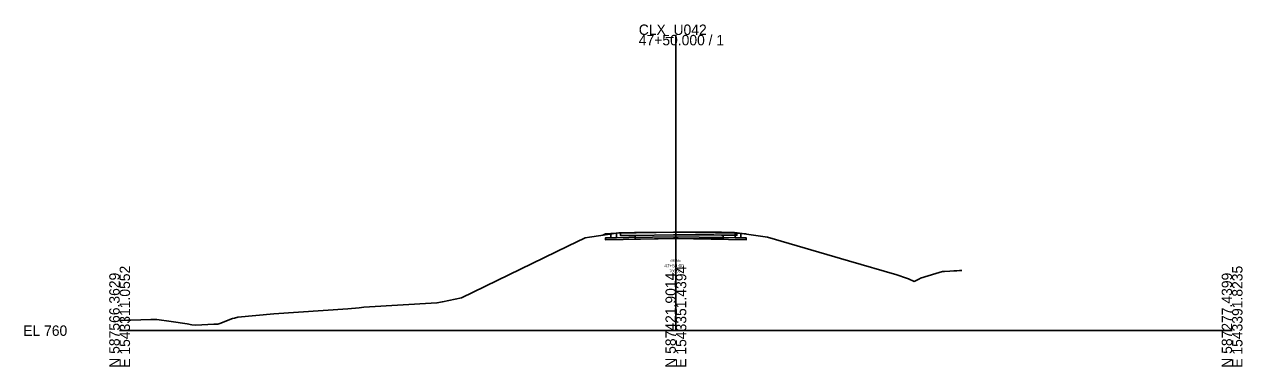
# Model space of a CAD drawing. Extents: x -26 to 1603, y -10 to 5557.
# Drawn here: x -25.7 to 302.8, y 3490.3 to 3582.5 of the extents above; entities that cross this region are included whole.
import ezdxf

# ---------------------------------------------------------------- set-up
doc = ezdxf.new("R2010")
doc.units = 0
for name, color, linetype in [('GK_Cells', 7, 'Continuous'), ('XS_P_Annotation', 7, 'Continuous'), ('XS_P_Earthwork_Shapes', 7, 'Continuous'), ('XS_P_Finished_Grade', 7, 'Continuous'), ('XS_P_Pavt_Layers', 7, 'Continuous'), ('XS_P_Pavt_Surface', 7, 'Continuous'), ('XS_P_Subgrade', 7, 'Continuous'), ('XS_X_Ground_Line', 7, 'Continuous'), ('XS_X_Pavt', 7, 'Continuous')]:
    doc.layers.add(name, color=color, linetype=linetype)

msp = doc.modelspace()

# ---------------------------------------------------------------- linework, layer by layer
at = {"layer": 'GK_Cells'}
for p, q in [((150, 3500), (150, 3579.69)), ((0, 3500), (150, 3500)), ((150, 3500), (300, 3500))]:
    msp.add_line(p, q, dxfattribs=at)
at = {"layer": 'XS_P_Earthwork_Shapes'}
for points in [[(131, 3526.05), (130.33, 3525.71), (134, 3526.28), (134, 3526.3)], [(134, 3526.3), (134, 3526.28), (130.33, 3525.71), (131, 3526.05)], [(131, 3526.05), (130.33, 3525.71), (132.5, 3526.05), (132.5, 3526.17)], [(131, 3525), (131, 3524.5), (150, 3524.8), (149.33, 3524.8), (139.01, 3524.66), (139.01, 3525.66), (138.82, 3525.66), (135.3, 3525.63), (135.11, 3525.63), (135.11, 3526.38), (134.65, 3526.37), (132.5, 3526.05), (132.5, 3525.02)], [(131, 3524.5), (150, 3524.8), (149.33, 3524.8), (139.01, 3524.66), (139.01, 3525.66), (138.82, 3525.66), (135.3, 3525.63), (135.11, 3525.63), (135.11, 3526.38), (134.65, 3526.37), (134, 3526.28), (134, 3525.05), (131, 3525)], [(131, 3524.5), (150, 3524.8), (149.33, 3524.8), (139.01, 3524.66), (139.01, 3525.66), (138.82, 3525.66), (135.3, 3525.63), (135.11, 3525.63), (135.11, 3526.38), (134.65, 3526.37), (134, 3526.28), (134, 3525.05), (131, 3525)], [(162.26, 3525.77), (162.76, 3525.76), (165.84, 3525.73), (166.44, 3525.65), (166.44, 3526.4), (165.84, 3526.48), (162.26, 3526.52), (160.23, 3526.53), (150.63, 3526.56), (150, 3526.55), (149.33, 3526.55), (138.82, 3526.41), (135.3, 3526.38), (135.11, 3526.38), (135.11, 3525.63), (135.3, 3525.63), (138.82, 3525.66), (139.01, 3525.66), (149.33, 3525.8), (150, 3525.8), (150.63, 3525.81), (160.23, 3525.78)], [(162.26, 3525.77), (162.76, 3525.76), (165.84, 3525.73), (166, 3525.71), (166, 3526.3), (166.44, 3526.26), (166.44, 3526.4), (165.84, 3526.48), (162.26, 3526.52), (160.23, 3526.53), (150.63, 3526.56), (150, 3526.55), (149.33, 3526.55), (138.82, 3526.41), (135.3, 3526.38), (135.11, 3526.38), (135.11, 3525.63), (135.3, 3525.63), (138.82, 3525.66), (139.01, 3525.66), (149.33, 3525.8), (150, 3525.8), (150.63, 3525.81), (160.23, 3525.78)], [(162.26, 3525.77), (162.76, 3525.76), (165.84, 3525.73), (166, 3525.71), (166, 3526.3), (166.44, 3526.26), (166.44, 3526.4), (165.84, 3526.48), (162.26, 3526.52), (160.23, 3526.53), (150.63, 3526.56), (150, 3526.55), (149.33, 3526.55), (138.82, 3526.41), (135.3, 3526.38), (135.11, 3526.38), (135.11, 3525.63), (135.3, 3525.63), (138.82, 3525.66), (139.01, 3525.66), (149.33, 3525.8), (150, 3525.8), (150.63, 3525.81), (160.23, 3525.78)], [(162.26, 3525.77), (162.76, 3525.76), (162.76, 3524.76), (162.26, 3524.77), (160.23, 3524.78), (150.63, 3524.81), (150, 3524.8), (149.33, 3524.8), (139.01, 3524.66), (139.01, 3525.66), (149.33, 3525.8), (150, 3525.8), (150.63, 3525.81), (160.23, 3525.78)], [(162.26, 3525.77), (162.76, 3525.76), (162.76, 3524.76), (162.26, 3524.77), (160.23, 3524.78), (150.63, 3524.81), (150, 3524.8), (149.33, 3524.8), (139.01, 3524.66), (139.01, 3525.66), (149.33, 3525.8), (150, 3525.8), (150.63, 3525.81), (160.23, 3525.78)], [(162.26, 3525.77), (162.76, 3525.76), (162.76, 3524.76), (162.26, 3524.77), (160.23, 3524.78), (150.63, 3524.81), (150, 3524.8), (149.33, 3524.8), (139.01, 3524.66), (139.01, 3525.66), (149.33, 3525.8), (150, 3525.8), (150.63, 3525.81), (160.23, 3525.78)], [(167.5, 3526.17), (168.69, 3526.07), (167.19, 3526.29), (166.44, 3526.4), (166.44, 3525.65), (165.84, 3525.73), (162.76, 3525.76), (162.76, 3524.76), (162.26, 3524.77), (160.23, 3524.78), (150.63, 3524.81), (150, 3524.8), (169, 3524.5), (169, 3525), (167.5, 3525.02)], [(150, 3524.8), (169, 3524.5), (169, 3525), (166, 3525.05), (166, 3525.71), (165.84, 3525.73), (162.76, 3525.76), (162.76, 3524.76), (162.26, 3524.77), (160.23, 3524.78), (150.63, 3524.81)], [(150, 3524.8), (169, 3524.5), (169, 3525), (166, 3525.05), (166, 3525.71), (165.84, 3525.73), (162.76, 3525.76), (162.76, 3524.76), (162.26, 3524.77), (160.23, 3524.78), (150.63, 3524.81)], [(166, 3526.3), (166.44, 3526.26), (166.44, 3525.65), (166, 3525.71)], [(166, 3526.3), (166.44, 3526.26), (166.44, 3525.65), (166, 3525.71)], [(167.19, 3526.29), (168.69, 3526.07), (166.44, 3526.26), (166.44, 3526.4)], [(167.19, 3526.29), (168.69, 3526.07), (166.44, 3526.26), (166.44, 3526.4)], [(169, 3526.05), (169.05, 3526.02), (168.69, 3526.07)], [(168.69, 3526.07), (169.05, 3526.02), (169, 3526.05)], [(168.69, 3526.07), (169.05, 3526.02), (169, 3526.05)]]:
    msp.add_lwpolyline(points, close=True, dxfattribs=at)
at = {"layer": 'XS_P_Finished_Grade'}
for p, q in [((131, 3526.05), (130.33, 3525.71)), ((134, 3526.3), (131, 3526.05)), ((166, 3526.3), (169, 3526.05)), ((169, 3526.05), (169.05, 3526.02))]:
    msp.add_line(p, q, dxfattribs=at)
at = {"layer": 'XS_P_Pavt_Layers'}
for p, q in [((150.02, 3525.3), (131, 3525)), ((134, 3526.3), (134, 3525.05)), ((149.98, 3525.3), (169, 3525)), ((166, 3526.3), (166, 3525.05)), ((131, 3524.5), (131, 3525)), ((150.03, 3524.8), (131, 3524.5)), ((149.97, 3524.8), (169, 3524.5)), ((169, 3524.5), (169, 3525))]:
    msp.add_line(p, q, dxfattribs=at)
at = {"layer": 'XS_P_Pavt_Surface'}
for q in [(134, 3526.3), (166, 3526.3)]:
    msp.add_line((150, 3526.55), q, dxfattribs=at)
at = {"layer": 'XS_P_Subgrade'}
msp.add_lwpolyline([(134, 3526.3), (134, 3525.05), (131, 3525), (131, 3524.5), (150, 3524.8), (169, 3524.5), (169, 3525), (166, 3525.05), (166, 3526.3)], dxfattribs=at)
at = {"layer": 'XS_X_Ground_Line'}
msp.add_lwpolyline([(0, 3502.74), (2.25, 3502.8), (3.02, 3502.83), (8.4, 3502.97), (10.05, 3503.02), (13.94, 3502.46), (18.22, 3501.8), (19.51, 3501.61), (20.58, 3501.44), (25.37, 3501.76), (26.44, 3501.75), (27.06, 3501.9), (30.47, 3503.27), (30.94, 3503.4), (31.86, 3503.65), (41.54, 3504.55), (61.58, 3505.92), (64.62, 3506.17), (65.84, 3506.29), (85.56, 3507.46), (87.04, 3507.78), (90.45, 3508.5), (92.16, 3508.87), (120.9, 3522.73), (125.58, 3524.98), (126.74, 3525.17), (134.65, 3526.37), (135.3, 3526.38), (138.82, 3526.41), (149.33, 3526.55), (150, 3526.55), (150.63, 3526.56), (160.23, 3526.53), (162.26, 3526.52), (165.84, 3526.48), (167.19, 3526.29), (174.73, 3525.2), (196.52, 3518.84), (209.57, 3515.01), (212.17, 3514.17), (212.77, 3513.98), (214.22, 3513.27), (215.66, 3513.96), (215.99, 3514.12), (220.14, 3515.41), (221.9, 3515.94), (222.47, 3515.97), (223.86, 3516.05), (224.94, 3516.1), (225.81, 3516.15), (226.52, 3516.19), (227.11, 3516.22)], dxfattribs=at)
at = {"layer": 'XS_X_Pavt'}
for p, q in [((135.11, 3526.38), (135.11, 3525.63)), ((135.11, 3525.63), (135.3, 3525.63)), ((135.3, 3525.63), (138.82, 3525.66)), ((138.82, 3525.66), (139.01, 3525.66)), ((139.01, 3525.66), (149.33, 3525.8)), ((139.01, 3525.66), (139.01, 3524.66)), ((149.33, 3525.8), (150, 3525.8)), ((150, 3525.8), (150.63, 3525.81)), ((150.63, 3525.81), (160.23, 3525.78)), ((160.23, 3525.78), (162.26, 3525.77)), ((162.26, 3525.77), (162.76, 3525.76)), ((162.76, 3525.76), (165.84, 3525.73)), ((162.76, 3525.76), (162.76, 3524.76)), ((165.84, 3525.73), (166.44, 3525.65)), ((166.44, 3526.4), (166.44, 3525.65)), ((139.01, 3524.66), (149.33, 3524.8)), ((149.33, 3524.8), (150, 3524.8)), ((150, 3524.8), (150.63, 3524.81)), ((150.63, 3524.81), (160.23, 3524.78)), ((160.23, 3524.78), (162.26, 3524.77)), ((162.26, 3524.77), (162.76, 3524.76))]:
    msp.add_line(p, q, dxfattribs=at)

# ---------------------------------------------------------------- texts
at = {"layer": 'GK_Cells'}
for s, p in [('CLX_U042', (140, 3579.69)), ('47+50.000 / 1', (140, 3576.89)), ('EL 760', (-26, 3498.6))]:
    msp.add_text(s, height=2.8, dxfattribs=at).set_placement(p)
for s, p in [('N 587566.3629', (0, 3490)), ('E 1543311.0552', (2.8, 3490)), ('N 587421.9014', (150, 3490)), ('E 1543351.4394', (152.8, 3490)), ('N 587277.4399', (300, 3490)), ('E 1543391.8235', (302.8, 3490))]:
    msp.add_text(s, height=2.8, rotation=90, dxfattribs=at).set_placement(p)
at = {"layer": 'XS_P_Annotation'}
for s, height, p in [('786.55', 0.7, (148.29, 3518.55)), ('47+50.00', 0.9, (146.9, 3517.05)), ('786.55', 0.7, (148.29, 3515.75))]:
    msp.add_text(s, height=height, dxfattribs=at).set_placement(p)

doc.saveas('drawing.dxf')
